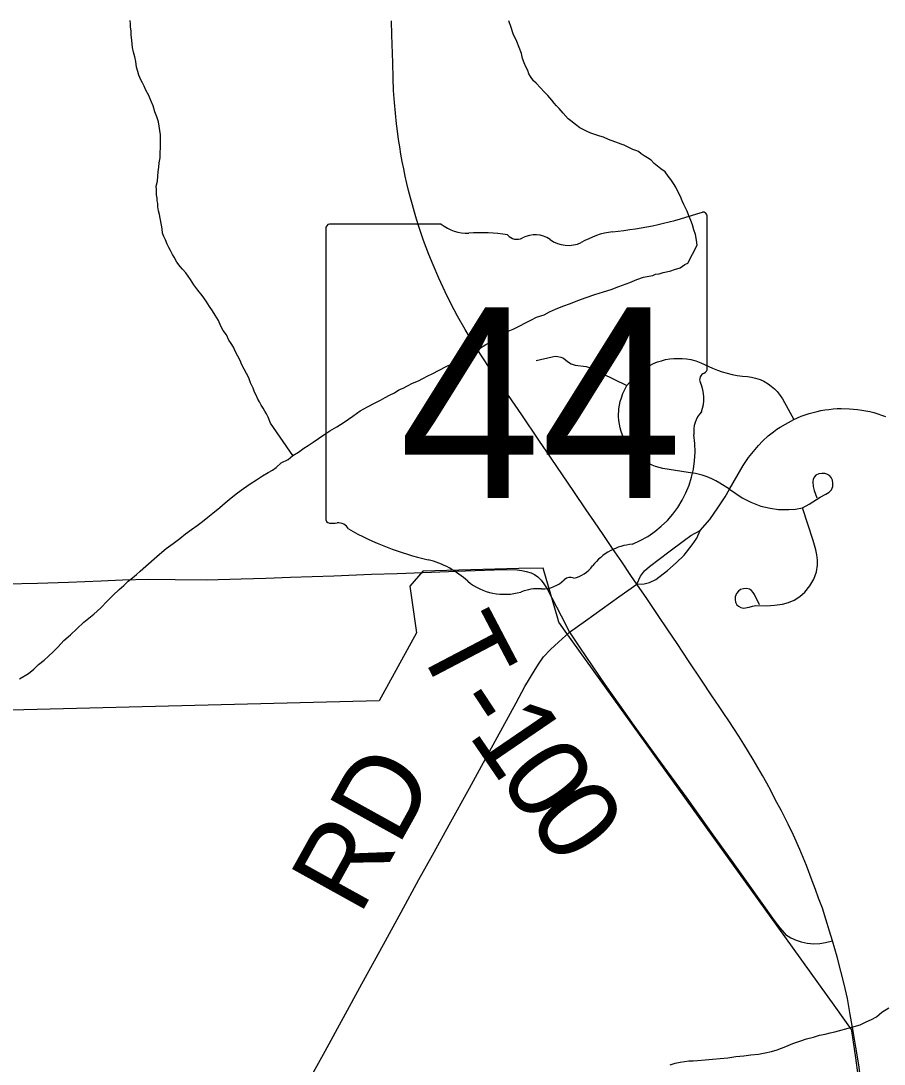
# Model space of a CAD drawing. Extents: x 103424 to 290657, y 38711 to 110967.
# Drawn here: x 143819 to 146990, y 92537 to 96372 of the extents above; entities that cross this region are included whole.
import ezdxf

# ---------------------------------------------------------------- set-up
doc = ezdxf.new("R2010")
doc.units = 0
for name, color, linetype in [('GM_X_City_Street', 7, 'Continuous'), ('GM_X_Corporation', 7, 'Continuous'), ('GM_X_County_Road', 7, 'Continuous'), ('GM_X_County_Road_Text', 7, 'Continuous'), ('GM_X_Major_River', 7, 'Continuous'), ('GM_X_Minor_River', 7, 'Continuous'), ('GM_X_State_Location', 7, 'Continuous'), ('GM_X_State_Route', 7, 'Continuous'), ('GM_X_State_Shield', 7, 'Continuous'), ('GM_X_Township_Road', 7, 'Continuous'), ('GM_X_Township_Road_Text', 7, 'Continuous')]:
    doc.layers.add(name, color=color, linetype=linetype)

msp = doc.modelspace()

# ---------------------------------------------------------------- linework, layer by layer
at = {"layer": 'GM_X_City_Street'}
for points in [[(145711.3, 95122.9), (145770.3, 95137.1), (145781.9, 95139.3), (145791.8, 95138.4), (145802.1, 95135.9), (145812, 95132), (145827.1, 95120.1), (145840.8, 95110.9), (145855.8, 95105.7), (145895.8, 95101.1), (145911.3, 95095.9), (145952.1, 95077), (146045.3, 95031.3)], [(146422, 94649.8), (146386.2, 94672.7), (146371.9, 94680.8), (146357, 94688.2), (146340.6, 94695.2), (146321.2, 94702.1), (146297.1, 94707.8), (146270.8, 94711.9), (146177.8, 94726.4), (146164, 94729.6), (146150.6, 94733.7), (146137.5, 94738.7), (146124.7, 94744.7), (146109.6, 94753.3), (146097.8, 94761.2), (146086.7, 94769.9), (146076.4, 94779.3), (146066.6, 94789.4), (146057.5, 94800.2), (146049.2, 94811.6), (146041.9, 94823.5), (146035.1, 94835.9), (146029.6, 94848.7), (146024.8, 94861.9), (146020.8, 94875.5), (146018.1, 94889.2), (146016, 94903.2), (146015, 94917.1), (146016, 94945.3), (146018.1, 94959.2), (146020.9, 94972.9), (146024.9, 94986.4), (146030.7, 95002), (146045.3, 95031.3), (146066.3, 95055), (146076.9, 95066.4), (146087.9, 95076.9), (146103.1, 95088.9), (146115.9, 95097.6), (146129.5, 95105.3), (146143.3, 95112.1), (146157.7, 95117.9), (146172.3, 95122.7), (146187.4, 95126.4), (146202.5, 95129.1), (146217.9, 95130.7), (146233.5, 95131.2), (146248.9, 95130.7), (146264.2, 95129), (146279.6, 95126.4), (146298.2, 95121.5), (146316.3, 95115.1), (146360.3, 95095.6), (146378, 95088.4), (146395.8, 95082), (146413.9, 95076.6), (146432.3, 95072.2), (146451, 95068.7), (146469.8, 95066.2), (146488.5, 95064.6), (146503.1, 95062.4), (146517.6, 95058.8), (146534.5, 95053.1), (146548.1, 95046.9), (146563.7, 95037.9), (146575.8, 95029.2), (146587.4, 95019.6), (146597.7, 95008.9), (146609, 94995), (146617.3, 94982.5), (146658.1, 94906.7)], [(146314.1, 94498), (146349.5, 94539.4), (146379.2, 94581.5), (146406.1, 94622.2), (146422, 94649.8), (146472.7, 94737.7), (146492.4, 94767), (146510.1, 94789.4), (146528.7, 94811.4), (146543.4, 94826.2), (146563.8, 94845.8), (146583.5, 94861.6), (146595.6, 94870.4), (146608.1, 94878.8), (146658.1, 94906.7), (146686.1, 94918.8), (146700.2, 94923.9), (146714.6, 94928.5), (146729.2, 94932.6), (146744, 94936.2), (146757.6, 94939.1), (146772.5, 94941.6), (146787.6, 94943.7), (146802.7, 94945.3), (146817.8, 94946.3), (146832.9, 94946.8), (146863.1, 94946.1), (146877.9, 94945), (146893.1, 94943.5), (146908.2, 94941.3), (146923, 94938.6), (146937.6, 94935.5), (146952.5, 94931.7), (146966.8, 94927.6), (146981.1, 94922.9), (146995.5, 94917.6)], [(146422, 94649.8), (146468.8, 94619), (146500.8, 94602.2), (146536.8, 94588.4), (146571.9, 94580), (146601.7, 94575.4), (146639.8, 94575), (146665.3, 94577), (146689.9, 94581.3), (146714.5, 94594.6), (146755.7, 94620.7), (146776.1, 94631.9), (146788.5, 94639.7), (146796.7, 94647.9), (146801.4, 94659.7), (146802.3, 94672.2), (146800.3, 94682.9), (146795.7, 94693.1), (146789.6, 94700.8), (146780.3, 94705.9), (146772.1, 94708), (146761.3, 94708.5), (146750.3, 94706.1), (146739.8, 94701.3), (146734.9, 94695.6), (146730, 94686.5), (146728.5, 94677.1), (146729.3, 94660.1), (146733.3, 94645.6), (146742.5, 94618.2)], [(146533, 94225.7), (146514.1, 94263.1), (146509.3, 94270.6), (146502.7, 94277.8), (146495.7, 94282.6), (146484.5, 94284.7), (146473.1, 94284.2), (146463.1, 94281.2), (146455.1, 94274.9), (146447.5, 94266.2), (146443.3, 94254.9), (146442.9, 94245.1), (146444.7, 94234.5), (146449, 94225.7), (146455.6, 94219.7), (146464.3, 94214.8), (146474.1, 94212.5), (146494.2, 94216.2), (146506.5, 94220.6), (146518.6, 94222.6), (146557.6, 94222), (146587.9, 94223.3), (146616.5, 94227.3), (146639.4, 94233.6), (146659.5, 94242.8), (146680.1, 94255.4), (146699.6, 94272), (146718, 94294.4), (146731.7, 94319), (146741.4, 94346.5), (146745.5, 94371.2), (146746, 94389.5), (146743.7, 94408.4), (146739.2, 94427.4), (146730, 94461.2), (146689.9, 94581.3)], [(146081.5, 94301.5), (146108.9, 94302), (146128.6, 94307.2), (146151.4, 94318.1), (146194.9, 94351), (146226.7, 94379.3), (146255.7, 94408.1), (146285.3, 94445.5), (146302.7, 94470.1), (146314.1, 94498)], [(146081.5, 94301.5), (146094.9, 94330), (146109.9, 94350.1), (146128.6, 94365.7), (146199.6, 94419.4), (146256.3, 94462.6), (146280.4, 94480.4), (146314.1, 94498)]]:
    msp.add_lwpolyline(points, dxfattribs=at)
at = {"layer": 'GM_X_Corporation'}
msp.add_lwpolyline([(146895.4, 92495.6), (146886.6, 92560.4), (146871.8, 92658.5), (146870.8, 92664.2), (146839.9, 92707.3), (146813, 92744.7), (146625.6, 93005.7), (145897.3, 94018.9), (145818.6, 94128.6), (145795.2, 94161.1), (145791.2, 94175.2), (145738.1, 94360.5), (145648.8, 94358.3), (145295.1, 94349.3), (145247.5, 94293.3), (145272.1, 94121.7), (145135.5, 93872.2), (143199.9, 93823.5)], dxfattribs=at)
at = {"layer": 'GM_X_County_Road'}
for points in [[(145834.2, 94124.9), (145893.3, 94166), (146016.2, 94254.4), (146081.5, 94301.5)], [(144869.2, 92463.4), (144936.8, 92584.7), (145004, 92708.4), (145071.1, 92832.2), (145150.5, 92976.9), (145215.7, 93095.9), (145280.9, 93214.9), (145336.6, 93315.7), (145392.3, 93416.5), (145466.4, 93551.1), (145540.5, 93685.6), (145589.5, 93775.4), (145638.4, 93865.3), (145670.7, 93925.5), (145708.1, 93987.4), (145722.4, 94010.3), (145739.1, 94033.7), (145765.1, 94061.5), (145793.4, 94088.1), (145834.2, 94124.9)]]:
    msp.add_lwpolyline(points, dxfattribs=at)
at = {"layer": 'GM_X_Major_River'}
for points in [[(146082.1, 95420.7), (146106.1, 95429.2), (146126.2, 95433.6), (146140.3, 95435.8), (146150.3, 95440.1), (146164.4, 95442.3), (146178.5, 95446.6), (146190.5, 95448.9), (146206.6, 95453.2), (146220.6, 95457.5), (146240.7, 95463.9), (146258.6, 95476.4), (146268.7, 95480.6)], [(143846.1, 93972.3), (143865.9, 93988.9), (143883.8, 94005.3), (143903.7, 94021.9), (143919.6, 94036.3), (143937.4, 94052.8), (143955.3, 94071.3), (143977.1, 94093.9), (144000.9, 94114.5), (144024.7, 94137.2), (144050.5, 94161.9), (144086.3, 94190.8), (144112.1, 94213.5), (144135.9, 94238.2), (144157.7, 94260.8), (144179.5, 94281.4), (144197.4, 94295.8), (144213.3, 94312.3), (144229.2, 94324.7), (144243.1, 94337.1), (144257, 94349.4), (144308.6, 94394.8), (144328.5, 94411.3), (144352.4, 94432), (144378.3, 94450.6), (144402.1, 94469.2), (144424, 94485.8), (144445.9, 94502.3), (144465.9, 94516.8), (144485.8, 94531.3), (144505.7, 94547.9), (144523.6, 94562.3), (144549.4, 94583), (144569.3, 94599.5), (144591.2, 94618.1), (144615, 94636.7), (144636.9, 94653.3), (144660.9, 94669.9), (144684.8, 94684.4), (144706.7, 94699), (144726.7, 94711.4), (144742.7, 94719.8), (144756.6, 94730.2), (144774.5, 94746.7), (144800.5, 94759.2), (144818.4, 94773.7), (144838.4, 94786.2), (144858.3, 94800.7), (144874.2, 94811.1), (144892.2, 94823.5), (144912.1, 94836), (144932, 94850.5), (144954, 94865), (144980, 94879.6), (145005.9, 94896.3), (145037.8, 94919.1), (145065.7, 94937.7), (145091.6, 94952.4), (145117.6, 94967), (145139.6, 94977.5), (145157.6, 94987.9), (145173.6, 94996.3), (145191.6, 95004.7), (145207.6, 95015), (145223.6, 95021.4), (145239.6, 95029.8), (145257.5, 95040.2), (145279.6, 95048.7), (145295.6, 95057), (145313.6, 95067.5), (145329.6, 95073.8), (145381.6, 95101), (145399.6, 95109.4), (145415.6, 95117.8), (145429.6, 95124.1), (145441.6, 95130.4), (145461.6, 95140.8), (145481.5, 95153.3), (145503.5, 95167.8), (145527.4, 95182.4), (145553.4, 95197), (145579.3, 95211.6), (145603.3, 95228.2), (145627.3, 95238.8), (145651.3, 95251.3), (145673.3, 95261.8), (145695.3, 95272.3), (145713.3, 95282.7), (145741.4, 95291.3), (145761.3, 95301.8), (145783.4, 95312.3), (145809.4, 95322.8), (145837.5, 95333.4), (145865.5, 95344), (145895.6, 95354.7), (145927.7, 95365.4), (145959.8, 95376), (145987.9, 95384.6), (146015.9, 95395.2), (146056, 95410.1), (146082.1, 95420.7)], [(143814.1, 93953.6), (143846.1, 93972.3)]]:
    msp.add_lwpolyline(points, dxfattribs=at)
at = {"layer": 'GM_X_Minor_River'}
for points in [[(144818.4, 94773.7), (144735.5, 94893.4), (144727.1, 94915.5), (144720.8, 94927.5), (144714.6, 94937.5), (144708.3, 94947.5), (144702.1, 94959.5), (144695.8, 94971.5), (144689.6, 94981.5), (144683.3, 94995.5), (144677, 95007.5), (144672.7, 95021.6), (144662.3, 95041.6), (144655.9, 95059.7), (144647.5, 95075.7), (144639.2, 95091.7), (144630.8, 95107.7), (144624.5, 95123.8), (144616.1, 95139.8), (144607.7, 95155.8), (144599.4, 95171.8), (144591.1, 95185.8), (144582.8, 95197.8), (144574.3, 95217.9), (144562, 95233.8), (144553.6, 95249.8), (144545.2, 95269.9), (144532.7, 95289.8), (144522.3, 95305.8), (144512, 95321.8), (144499.5, 95341.8), (144485, 95361.7), (144468.5, 95381.6), (144454, 95401.6), (144441.6, 95421.5), (144425, 95445.5), (144412.6, 95459.4), (144404.4, 95469.4), (144392, 95485.3), (144381.6, 95503.3), (144375.3, 95513.3), (144369, 95527.3), (144362.8, 95539.3), (144356.5, 95551.4), (144350.1, 95567.4), (144343.9, 95579.4), (144339.6, 95591.5), (144337.3, 95607.6), (144328.3, 95659.9), (144324, 95674), (144321.8, 95688.1), (144321.5, 95700.2), (144319.3, 95710.3), (144319.2, 95720.4), (144316.9, 95732.5), (144316.6, 95752.7), (144316.3, 95764.8), (144320.1, 95783), (144321.7, 95801.3), (144323.5, 95817.5), (144325.2, 95833.6), (144326.9, 95849.8), (144330.6, 95868.1), (144330.3, 95886.3), (144332, 95906.5), (144331.7, 95922.7), (144331.4, 95938.8), (144331.1, 95953), (144328.8, 95969.1), (144326.5, 95985.2), (144324.2, 96001.3), (144317.8, 96019.4), (144311.4, 96037.5), (144305, 96059.6), (144296.6, 96079.6), (144288.2, 96097.6), (144277.7, 96117.7), (144271.4, 96131.7), (144265.2, 96143.7), (144258.9, 96155.7), (144252.5, 96171.8), (144248.2, 96185.8), (144243.9, 96201.9), (144241.5, 96222.1), (144237.2, 96240.2), (144232.9, 96256.3), (144228.5, 96274.4), (144226, 96300.6), (144223.7, 96318.7), (144223.4, 96334.9), (144221.1, 96349), (144220.9, 96361.1), (144220.7, 96373.2)], [(146268.7, 95480.6), (146303.8, 95547.9), (146301.4, 95566), (146297, 95586.1), (146290.6, 95604.2), (146286.3, 95622.3), (146280, 95638.4), (146271.5, 95658.4), (146267.2, 95672.5), (146261, 95684.5), (146254.7, 95696.5), (146248.4, 95710.5), (146242, 95726.6), (146233.7, 95742.6), (146225.3, 95760.6), (146217, 95774.6), (146206.6, 95788.6), (146196.3, 95800.5), (146185.9, 95816.5), (146169.6, 95828.3), (146157.3, 95838.2), (146145, 95848.1), (146134.7, 95860), (146120.5, 95867.8), (146108.2, 95875.7), (146098, 95883.6), (146087.8, 95891.5), (146077.6, 95895.4), (146067.4, 95899.2), (146047.1, 95909), (146034.9, 95914.8), (146024.7, 95918.7), (146014.5, 95922.5), (145978, 95936), (145959.7, 95943.8), (145945.5, 95947.5), (145931.3, 95953.4), (145913, 95959.1), (145898.8, 95964.9), (145886.6, 95970.7), (145872.3, 95978.6), (145855.9, 95990.4), (145839.5, 96004.2), (145829.3, 96012.1), (145810.8, 96032), (145796.4, 96049.9), (145786.1, 96059.9), (145777.8, 96069.8), (145769.6, 96079.8), (145755.1, 96097.7), (145740.8, 96111.6), (145728.4, 96125.5), (145712, 96143.4), (145701.7, 96151.3), (145691.3, 96167.2), (145685.1, 96177.2), (145680.8, 96189.3), (145674.5, 96203.3), (145668.2, 96217.3), (145661.9, 96233.4), (145657.5, 96251.5), (145649.1, 96273.6), (145640.6, 96295.6), (145628, 96323.7), (145619.5, 96347.8), (145611, 96371.9)], [(146204.5, 92533.7), (146222.6, 92540.1), (146240.6, 92544.5), (146256.7, 92546.8), (146272.8, 92549.1), (146289, 92549.4), (146305.1, 92549.7), (146333.3, 92552.2), (146359.5, 92554.7), (146387.7, 92557.2), (146415.9, 92559.7), (146446.1, 92564.3), (146474.3, 92566.9), (146500.4, 92571.4), (146528.7, 92573.9), (146552.8, 92578.4), (146576.9, 92582.8), (146597, 92589.3), (146629, 92602), (146655.1, 92612.5), (146681.2, 92621.1), (146705.2, 92629.6), (146731.3, 92636.1), (146753.4, 92642.6), (146773.5, 92647), (146791.6, 92651.3), (146809.7, 92655.7), (146871.9, 92673), (146902, 92681.6), (146924, 92692.1), (146944.1, 92700.5), (146962.1, 92711), (146981.9, 92727.5), (147007.9, 92744.1)]]:
    msp.add_lwpolyline(points, dxfattribs=at)
at = {"layer": 'GM_X_State_Route'}
for points in [[(146876.6, 92657.8), (146866, 92719.7), (146856, 92778), (146843.6, 92831), (146831.8, 92878.7), (146817.7, 92931.7), (146801.1, 92990.3), (146790, 93025.2), (146775.8, 93069.5), (146763.5, 93109.6), (146749.4, 93147.3), (146738.2, 93179.1), (146726.4, 93210.3), (146705.1, 93266.6), (146680.9, 93326.2), (146657.3, 93377.9), (146637.6, 93418.5), (146612.7, 93467.7), (146590.4, 93509.9), (146574.8, 93539.6), (146559, 93569.1), (146542.9, 93598.3), (146526.3, 93627.4), (146509.4, 93656.3), (146492.1, 93685), (146474.7, 93713.5), (146456.9, 93741.8), (146438.5, 93770), (146420.1, 93798.1), (146401.5, 93826), (146384.8, 93851), (146357.9, 93891.1), (146319.6, 93948.3), (146271.8, 94019.7), (146229.9, 94082.4), (146195.6, 94133.6), (146157.4, 94189.8), (146117.9, 94247.9), (146081.5, 94301.5), (146060.3, 94332.7), (146026.1, 94383), (145992.8, 94432), (145957.7, 94483.7), (145926.1, 94530.1), (145895.7, 94574.9), (145850.6, 94641.3), (145808.3, 94703.5), (145766.9, 94764.5), (145721.8, 94830.8), (145659.1, 94923.1), (145585.4, 95030.8), (145544.6, 95089.8), (145511.3, 95140.6), (145478.6, 95191.4), (145451.2, 95236.9), (145422.5, 95286.5), (145398, 95332.6), (145377, 95375.8), (145353.7, 95426.6), (145333.2, 95475.1), (145317.7, 95513.3), (145308.1, 95538.9), (145298.5, 95564.6), (145289.5, 95590.4), (145281, 95616.4), (145272.7, 95642.5), (145264.6, 95668.7), (145257.1, 95695), (145250, 95721.4), (145243.3, 95747.9), (145236.7, 95774.5), (145230.7, 95801.2), (145225.2, 95828), (145219.7, 95854.8), (145214.9, 95881.7), (145210.4, 95908.7), (145206.4, 95935.8), (145201.1, 95975.7), (145198.8, 95993.6), (145194.6, 96032.6), (145191.3, 96071.8), (145188.3, 96116.5), (145186.8, 96160.9), (145184.8, 96217.5), (145182, 96320.2), (145180.9, 96372.1)], [(146876.6, 92657.8), (146866, 92719.7), (146856, 92778), (146843.6, 92831), (146831.8, 92878.7), (146817.7, 92931.7), (146801.1, 92990.3), (146790, 93025.2), (146775.8, 93069.5), (146763.5, 93109.6), (146749.4, 93147.3), (146738.2, 93179.1), (146726.4, 93210.3), (146705.1, 93266.6), (146680.9, 93326.2), (146657.3, 93377.9), (146637.6, 93418.5), (146612.7, 93467.7), (146590.4, 93509.9), (146574.8, 93539.6), (146559, 93569.1), (146542.9, 93598.3), (146526.3, 93627.4), (146509.4, 93656.3), (146492.1, 93685), (146474.7, 93713.5), (146456.9, 93741.8), (146438.5, 93770), (146420.1, 93798.1), (146401.5, 93826), (146384.8, 93851), (146357.9, 93891.1), (146319.6, 93948.3), (146271.8, 94019.7), (146229.9, 94082.4), (146195.6, 94133.6), (146157.4, 94189.8), (146117.9, 94247.9), (146081.5, 94301.5), (146060.3, 94332.7), (146026.1, 94383), (145992.8, 94432), (145957.7, 94483.7), (145926.1, 94530.1), (145895.7, 94574.9), (145850.6, 94641.3), (145808.3, 94703.5), (145766.9, 94764.5), (145721.8, 94830.8), (145659.1, 94923.1), (145585.4, 95030.8), (145544.6, 95089.8), (145511.3, 95140.6), (145478.6, 95191.4), (145451.2, 95236.9), (145422.5, 95286.5), (145398, 95332.6), (145377, 95375.8), (145353.7, 95426.6), (145333.2, 95475.1), (145317.7, 95513.3), (145308.1, 95538.9), (145298.5, 95564.6), (145289.5, 95590.4), (145281, 95616.4), (145272.7, 95642.5), (145264.6, 95668.7), (145257.1, 95695), (145250, 95721.4), (145243.3, 95747.9), (145236.7, 95774.5), (145230.7, 95801.2), (145225.2, 95828), (145219.7, 95854.8), (145214.9, 95881.7), (145210.4, 95908.7), (145206.4, 95935.8), (145201.1, 95975.7), (145198.8, 95993.6), (145194.6, 96032.6), (145191.3, 96071.8), (145188.3, 96116.5), (145186.8, 96160.9), (145184.8, 96217.5), (145182, 96320.2), (145180.9, 96372.1)], [(146936, 92254.1), (146928.4, 92308.8), (146919.7, 92370.5), (146907.7, 92456.6), (146897, 92533.8), (146886.3, 92598.9), (146876.6, 92657.8)], [(146936, 92254.1), (146928.4, 92308.8), (146919.7, 92370.5), (146907.7, 92456.6), (146897, 92533.8), (146886.3, 92598.9), (146876.6, 92657.8)]]:
    msp.add_lwpolyline(points, dxfattribs=at)
at = {"layer": 'GM_X_State_Shield'}
for p, q in [((146340.2, 95095), (146340.2, 95651.2)), ((145363.4, 95624.8), (144953.1, 95624.8)), ((144939.3, 95606.5), (144939.3, 94543.3)), ((146340, 95095.1), (146340.2, 95095))]:
    msp.add_line(p, q, dxfattribs=at)
for centre, radius, start, end in [((145841.2, 97074.4), 1485.6, 275.8445, 288.9065), ((146324.6, 95653.5), 15.6, 351.8621, 97.738), ((144955.4, 95608.8), 16.2, 98.1301, 188.1301), ((145461.1, 95748.2), 157.4, 231.6195, 271.1119), ((145513.2, 95027.9), 565.1, 80.4867, 94.9883), ((145641.5, 95614.3), 45.4, 219.7921, 297.1024), ((145708.2, 95491.4), 94.4, 54.4667, 119.1411), ((146030.7, 95300.1), 298.9, 97.3462, 120.7689), ((145830.1, 95660), 113.6, 233.8562, 294.8282), ((146336.6, 95054.1), 24.1, 107.944, 210.337), ((146323.5, 95092.8), 16.7, 289.6038, 7.7341), ((146183, 94983.8), 144.9, 340.033, 23.6496), ((146396, 94862.2), 105.4, 136.8065, 186.9296), ((145924.4, 94791.5), 371.6, 292.3089, 8.9858), ((144955.5, 94541), 16.4, 171.9584, 258.3066), ((144958, 94649.7), 124.9, 267.339, 280.6039), ((144983.6, 94481.9), 45.1, 29.7484, 93.2717), ((145552.4, 95437.2), 1072.8, 240.4129, 257.1985), ((146081.1, 94244.8), 203.5, 94.4031, 142.5768), ((145232.5, 94065.6), 335.7, 47.1842, 75.836), ((145823.2, 94440.2), 120, 282.8732, 323.2771), ((145595.6, 94476.7), 213, 230.7004, 286.2918), ((145734.2, 94397.1), 113.5, 268.777, 315.5493), ((145836.8, 94294.1), 32, 65.7517, 132.6484), ((145718.6, 94109.1), 175, 85.6951, 111.2099)]:
    msp.add_arc(centre, radius, start, end, dxfattribs=at)
at = {"layer": 'GM_X_Township_Road'}
for points in [[(145295, 94344.2), (145452.1, 94350.5), (145592.7, 94355.2), (145642, 94354.3), (145659.7, 94351.7), (145675.1, 94348.1), (145693.3, 94342.8), (145705.8, 94337), (145718.2, 94328.6), (145729.7, 94316.2), (145740.5, 94301.8), (145751.8, 94283.5), (145803.4, 94184.1), (145834.2, 94124.9)], [(142937.2, 94278.7), (143035.5, 94279.6), (143141.8, 94281.8), (143257.9, 94284.9), (143409, 94291.2), (143501.3, 94295.1), (143593.5, 94298.9), (143678.2, 94300.6), (143762.9, 94302.2), (143880.3, 94304.4), (143994.1, 94307.9), (144114.2, 94313.2), (144191.7, 94317.2), (144289.1, 94319), (144385.3, 94317.7), (144501.8, 94317.2), (144628.4, 94320.3), (144718.6, 94323.3), (144808.9, 94326.3), (144968.7, 94331.4), (145107.3, 94337.6), (145201.2, 94340.9), (145295, 94344.2)], [(145834.2, 94124.9), (145871, 94069), (145917.7, 94000.6), (145964.4, 93932.2), (146017.9, 93856.7), (146071.3, 93781.2), (146168.1, 93647.6), (146265, 93513.9), (146361.3, 93379.9), (146428.8, 93286), (146496.3, 93192.2), (146586.1, 93065), (146606.8, 93037.5), (146622.5, 93019.5)], [(146622.5, 93019.5), (146628.1, 93013.7), (146647.5, 93000.6), (146666.9, 92991.8), (146685.2, 92986.5), (146707.5, 92981.8), (146732.3, 92979.4), (146753.6, 92980.3), (146775.3, 92983.4), (146801.1, 92990.3)]]:
    msp.add_lwpolyline(points, dxfattribs=at)

# ---------------------------------------------------------------- texts
at = {"layer": 'GM_X_County_Road_Text'}
msp.add_text('RD', height=301.87, rotation=60.9941, dxfattribs=at).set_placement((145063.1, 93078.8))
at = {"layer": 'GM_X_State_Location'}
for s, p in [('s', (145624, 95004.2)), ('r', (145623.9, 95004.2))]:
    msp.add_text(s, height=1.01, dxfattribs=at).set_placement(p)
msp.add_text('44', height=1.01, rotation=0, dxfattribs=at).set_placement((145370.6, 94931))
at = {"layer": 'GM_X_State_Shield'}
msp.add_text('44', height=700.44, dxfattribs=at).set_placement((145208.1, 94618.3))
at = {"layer": 'GM_X_Township_Road_Text'}
for s, rotation, p in [('T', 297.6767, (145266.6, 94085.7)), ('-', 303.2998, (145387.8, 93857.9)), ('1', 304.3258, (145459.2, 93749.4)), ('0', 305.3884, (145567.5, 93590.8)), ('0', 305.6826, (145676.2, 93437.9))]:
    msp.add_text(s, height=301.9, rotation=rotation, dxfattribs=at).set_placement(p)

doc.saveas('drawing.dxf')
